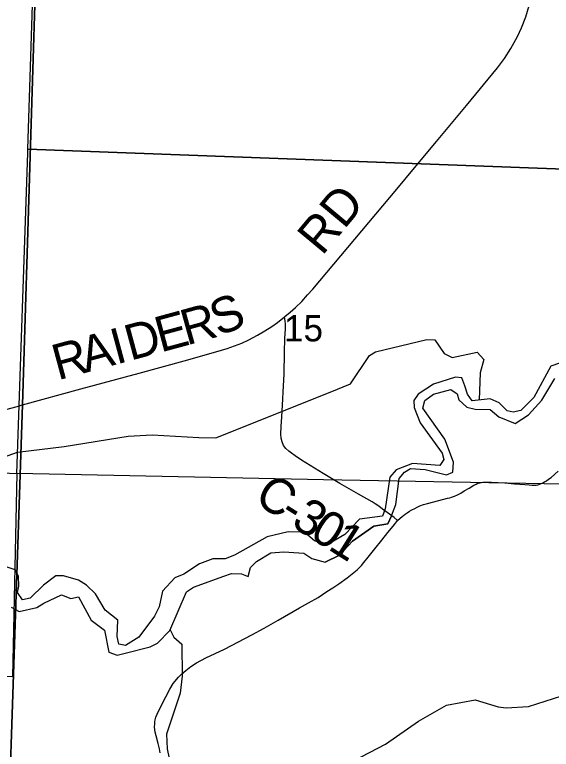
# Model space of a CAD drawing. Extents: x 0 to 34, y 0 to 22.
# Drawn here: x 6.135 to 6.991, y 18.295 to 19.468 of the extents above; entities that cross this region are included whole.
import ezdxf

# ---------------------------------------------------------------- set-up
doc = ezdxf.new("R2010")
doc.units = 0
for name, color, linetype in [('GM_X_County_Road', 7, 'Continuous'), ('GM_X_County_Road_Text', 7, 'Continuous'), ('GM_X_Minor_River', 7, 'Continuous'), ('GM_X_Section', 7, 'Continuous'), ('GM_X_Section_Text', 7, 'Continuous'), ('GM_X_Township', 7, 'Continuous')]:
    doc.layers.add(name, color=color, linetype=linetype)

msp = doc.modelspace()

# ---------------------------------------------------------------- linework, layer by layer
at = {"layer": 'GM_X_County_Road'}
for points in [[(6.5654, 18.9855), (6.5662, 18.9862), (6.5744, 18.9928), (6.5831, 19.0004), (6.5934, 19.0103), (6.6023, 19.0206), (6.6105, 19.0299), (6.7446, 19.1893), (6.773, 19.2233), (6.8083, 19.2657), (6.8562, 19.3229), (6.9056, 19.383), (6.9167, 19.398), (6.9267, 19.4138), (6.9374, 19.4329), (6.944, 19.447), (6.9507, 19.4645), (6.9561, 19.4824)], [(6.1467, 18.8449), (6.1473, 18.845), (6.2406, 18.8704), (6.3333, 18.8957), (6.4052, 18.9151), (6.4561, 18.9295), (6.4739, 18.9349), (6.4856, 18.9391), (6.4971, 18.9438), (6.5084, 18.9491), (6.5222, 18.9564), (6.5343, 18.9634), (6.5453, 18.9704), (6.5544, 18.9767), (6.5654, 18.9855)], [(6.7457, 18.6607), (6.7403, 18.665), (6.7221, 18.6788), (6.7188, 18.6813), (6.7146, 18.6844), (6.7104, 18.6871), (6.7052, 18.6905), (6.6835, 18.7026), (6.6536, 18.7193), (6.6271, 18.7356), (6.5927, 18.757), (6.5824, 18.7637), (6.5764, 18.7681), (6.5723, 18.7711), (6.5678, 18.7754), (6.5641, 18.7803), (6.5615, 18.7859), (6.5599, 18.7919), (6.5596, 18.7981), (6.5601, 18.8105), (6.5614, 18.8259), (6.5625, 18.8445), (6.5639, 18.8756), (6.5647, 18.8942), (6.5655, 18.9287), (6.5662, 18.9508), (6.5669, 18.9662), (6.567, 18.97), (6.5669, 18.9742), (6.5666, 18.9787), (6.5654, 18.9855)], [(5.9832, 18.7991), (6.0938, 18.8307), (6.1387, 18.8427), (6.1467, 18.8449)], [(6.7457, 18.6607), (6.7536, 18.6672), (6.7555, 18.6686), (6.7581, 18.6706), (6.7614, 18.6729), (6.7649, 18.6751), (6.7689, 18.6776), (6.7733, 18.6797), (6.777, 18.6819), (6.7814, 18.6837), (6.7875, 18.6858), (6.7939, 18.6878), (6.8037, 18.6904), (6.8257, 18.696), (6.8292, 18.6969), (6.832, 18.6976), (6.8369, 18.6994), (6.8416, 18.7015), (6.8469, 18.7041), (6.8524, 18.7076), (6.8603, 18.7123), (6.8678, 18.7166), (6.8713, 18.7185), (6.8742, 18.7198), (6.8771, 18.7207), (6.8801, 18.7213), (6.8821, 18.7216), (6.8844, 18.7217), (6.8869, 18.7218), (6.8957, 18.7217), (6.9174, 18.7206), (6.9328, 18.7192), (6.9413, 18.7184), (6.9492, 18.7177), (6.9558, 18.7172), (6.9604, 18.7171), (6.9629, 18.717), (6.9653, 18.717), (6.9673, 18.7171), (6.9701, 18.7175), (6.9717, 18.718), (6.9743, 18.7189), (6.9781, 18.7208), (6.9807, 18.7222), (6.9835, 18.7237), (6.987, 18.7262), (6.991, 18.7293), (7.0024, 18.7392)], [(6.3671, 18.2897), (6.3661, 18.2957), (6.3639, 18.3047), (6.3605, 18.3167), (6.3592, 18.3228), (6.3584, 18.3265), (6.3581, 18.331), (6.3583, 18.3353), (6.3586, 18.3393), (6.3592, 18.3421), (6.3603, 18.3464), (6.3624, 18.3511), (6.3659, 18.3593), (6.3761, 18.3792), (6.3824, 18.391), (6.3879, 18.4002), (6.3961, 18.4103), (6.4008, 18.4152), (6.4077, 18.4212), (6.4162, 18.4273), (6.4251, 18.4333), (6.4399, 18.441), (6.4699, 18.4553), (6.5135, 18.4782), (6.5331, 18.4888), (6.5555, 18.5013), (6.5893, 18.5208), (6.6039, 18.5289), (6.6191, 18.5377), (6.6333, 18.5469), (6.6425, 18.5529), (6.6524, 18.5594), (6.6653, 18.5688), (6.6815, 18.5815), (6.6884, 18.5885), (6.6921, 18.5933), (6.6989, 18.602), (6.7096, 18.6153), (6.7206, 18.6293), (6.7305, 18.6411), (6.7365, 18.6482), (6.7411, 18.6542), (6.7457, 18.6607)]]:
    msp.add_lwpolyline(points, dxfattribs=at)
at = {"layer": 'GM_X_Minor_River'}
for points in [[(6.0884, 18.7515), (6.1391, 18.7696), (6.2137, 18.7786), (6.316, 18.795), (6.3542, 18.7971), (6.4289, 18.7928), (6.4558, 18.7926), (6.6382, 18.8651), (6.6711, 18.8785), (6.7012, 18.9238), (6.711, 18.9295), (6.7928, 18.9496), (6.8057, 18.9489), (6.8206, 18.9269), (6.8331, 18.9205), (6.8729, 18.9294), (6.8836, 18.9173), (6.878, 18.8961), (6.8761, 18.8529)], [(7.0044, 18.9117), (6.9908, 18.9068), (6.9634, 18.857), (6.9427, 18.836), (6.9306, 18.8333), (6.9211, 18.8356), (6.9082, 18.8484), (6.8938, 18.8548), (6.865, 18.8517), (6.8578, 18.8623), (6.8532, 18.8756), (6.8486, 18.8884), (6.8387, 18.8892), (6.8036, 18.878), (6.779, 18.862), (6.7722, 18.8521), (6.7723, 18.8408), (6.7822, 18.8165), (6.8173, 18.7681), (6.82, 18.7578), (6.8136, 18.748), (6.7697, 18.7516), (6.7436, 18.7413), (6.7338, 18.7298), (6.7264, 18.679), (6.7219, 18.6676)], [(6.7352, 18.6654), (6.7434, 18.6862), (6.7486, 18.7276), (6.7568, 18.7375), (6.7667, 18.7432), (6.7898, 18.7418), (6.8239, 18.7336), (6.8341, 18.7378), (6.8355, 18.7537), (6.8213, 18.7905), (6.7863, 18.84), (6.7897, 18.8522), (6.8032, 18.8621), (6.8308, 18.8698), (6.8411, 18.8626), (6.8438, 18.8531), (6.8563, 18.8414), (6.87, 18.8381), (6.8938, 18.8378), (6.9075, 18.8257), (6.9337, 18.8155), (6.9552, 18.8293), (6.9763, 18.8525), (6.9973, 18.8871)], [(6.7362, 18.6679), (6.7434, 18.6862), (6.7486, 18.7276), (6.7568, 18.7375), (6.7667, 18.7432), (6.7898, 18.7418), (6.8239, 18.7336), (6.8341, 18.7378), (6.8355, 18.7537), (6.8213, 18.7905), (6.7863, 18.84), (6.7897, 18.8522), (6.8032, 18.8621), (6.8308, 18.8698), (6.8411, 18.8626), (6.8438, 18.8531), (6.8563, 18.8414), (6.87, 18.8381), (6.8938, 18.8378), (6.9075, 18.8257), (6.9337, 18.8155), (6.9552, 18.8293), (6.9763, 18.8525), (6.9973, 18.8871)], [(6.7219, 18.6676), (6.6854, 18.6627), (6.6616, 18.6379), (6.6374, 18.6238), (6.6257, 18.6237), (6.6135, 18.6278), (6.6025, 18.6373), (6.5915, 18.6418), (6.5714, 18.6425)], [(6.6303, 18.5938), (6.6534, 18.6053), (6.6742, 18.6277), (6.7082, 18.6514), (6.7305, 18.6549), (6.7362, 18.6679)], [(6.7362, 18.6679), (6.7305, 18.6549), (6.7082, 18.6514), (6.6742, 18.6277), (6.6534, 18.6053), (6.6303, 18.5938)], [(6.5714, 18.6425), (6.5377, 18.6343), (6.4859, 18.6049), (6.4707, 18.5991), (6.451, 18.5991), (6.4298, 18.5914), (6.4049, 18.575), (6.3902, 18.5688), (6.3709, 18.5475)], [(6.2986, 18.4455), (6.313, 18.4494), (6.3512, 18.4586), (6.3626, 18.4644), (6.3826, 18.4846), (6.4088, 18.5465), (6.4202, 18.5542), (6.4686, 18.5718), (6.4811, 18.5761), (6.497, 18.5754), (6.5076, 18.5709), (6.5114, 18.5853), (6.5208, 18.5952), (6.5439, 18.6086), (6.5643, 18.6106), (6.5962, 18.6084), (6.6091, 18.5997), (6.6303, 18.5938)], [(6.3709, 18.5475), (6.3653, 18.5228), (6.3582, 18.5076), (6.333, 18.4741), (6.3118, 18.4611), (6.3012, 18.463), (6.2985, 18.4755), (6.2995, 18.5013), (6.2793, 18.5171), (6.2637, 18.5432), (6.2496, 18.5572), (6.2367, 18.5651), (6.2127, 18.5722), (6.2006, 18.5722), (6.1806, 18.5573), (6.1595, 18.5363), (6.1474, 18.534), (6.139, 18.5457), (6.1416, 18.5556), (6.1407, 18.5715), (6.1354, 18.5818), (6.1229, 18.5859)], [(6.1292, 18.5222), (6.1418, 18.515), (6.1701, 18.5216), (6.1815, 18.5285), (6.2095, 18.5419), (6.2243, 18.5359), (6.2364, 18.5386), (6.257, 18.5011), (6.2783, 18.4856), (6.2853, 18.4504), (6.2986, 18.4455)], [(6.3831, 18.4858), (6.3887, 18.4744), (6.4016, 18.463), (6.4019, 18.4118), (6.399, 18.3849), (6.3773, 18.3195), (6.3781, 18.296), (6.3851, 18.2627)], [(6.3977, 18.2296), (6.4186, 18.2279), (6.4369, 18.2086), (6.4495, 18.1836), (6.4761, 18.1773), (6.547, 18.1723), (6.5572, 18.1724), (6.5992, 18.1968), (6.6211, 18.217), (6.644, 18.2543), (6.6758, 18.2768), (6.7268, 18.3032), (6.7793, 18.3399), (6.8243, 18.3659), (6.8701, 18.374), (6.9066, 18.3628), (6.9191, 18.3613), (6.9551, 18.3638), (7.0213, 18.3846), (7.0444, 18.396), (7.0804, 18.403), (7.105, 18.4039), (7.1512, 18.4086)]]:
    msp.add_lwpolyline(points, dxfattribs=at)
at = {"layer": 'GM_X_Section'}
for points in [[(6.1908, 20.2736), (7.0795, 20.2374), (7.0553, 19.2199), (6.1559, 19.253), (6.1718, 19.7471), (6.1903, 20.2549), (6.1905, 20.2588)], [(6.1559, 19.253), (7.0553, 19.2199), (7.0388, 18.7177), (6.6277, 18.7256), (6.1384, 18.7353), (6.1557, 19.2472)], [(5.6053, 18.7602), (6.1384, 18.7353), (6.1311, 18.4108), (5.1195, 18.4619), (5.1294, 18.7895)]]:
    msp.add_lwpolyline(points, close=True, dxfattribs=at)
at = {"layer": 'GM_X_Township'}
for points in [[(2.6013, 16.5379), (2.8688, 16.5234), (3.5006, 16.5009), (4.2928, 16.4705), (5.2983, 16.434), (6.0664, 16.4042), (6.0778, 16.7443), (6.0911, 17.2548), (6.11, 17.7459), (6.1473, 18.845), (6.1717, 19.6397), (6.1731, 19.6616), (6.1731, 19.6818), (6.1733, 19.6859), (6.2234, 21.2003)], [(6.2234, 21.2003), (6.1733, 19.6859), (6.1731, 19.6818), (6.1731, 19.6616), (6.1717, 19.6397), (6.1473, 18.845), (6.11, 17.7459), (6.0911, 17.2548), (6.0778, 16.7443), (6.0664, 16.4042), (6.0598, 16.2379), (6.2085, 16.2337), (6.3056, 16.228), (6.5048, 16.2253), (7.5772, 16.1862), (7.7357, 16.1804), (8.4842, 16.1527), (8.5405, 16.1503), (9.1818, 16.131), (9.4013, 16.1226)]]:
    msp.add_lwpolyline(points, dxfattribs=at)

# ---------------------------------------------------------------- texts
at = {"layer": 'GM_X_County_Road_Text'}
for s, height, rotation, p in [('RD', 0.05682, 50.2578, (6.6255, 19.0818)), ('S', 0.0568, 21.3099, (6.46, 18.9542)), ('R', 0.0568, 15.5998, (6.4092, 18.9397)), ('E', 0.0568, 15.1275, (6.3677, 18.9285)), ('D', 0.0568, 15.1251, (6.3194, 18.9154)), ('I', 0.0568, 15.123, (6.2969, 18.9093)), ('A', 0.0568, 15.1251, (6.2486, 18.8963)), ('R', 0.0568, 15.123, (6.2036, 18.8841)), ('C', 0.0568, 326.3797, (6.5148, 18.6913)), ('3', 0.0568, 327.7858, (6.5742, 18.6525)), ('-', 0.0568, 327.7729, (6.5546, 18.6648)), ('0', 0.0568, 327.7925, (6.6036, 18.634)), ('1', 0.0568, 327.7945, (6.633, 18.6155))]:
    msp.add_text(s, height=height, rotation=rotation, dxfattribs=at).set_placement(p)
at = {"layer": 'GM_X_Section_Text'}
msp.add_text('15', height=0.04186, rotation=0, dxfattribs=at).set_placement((6.5647, 18.9464))

doc.saveas('drawing.dxf')
